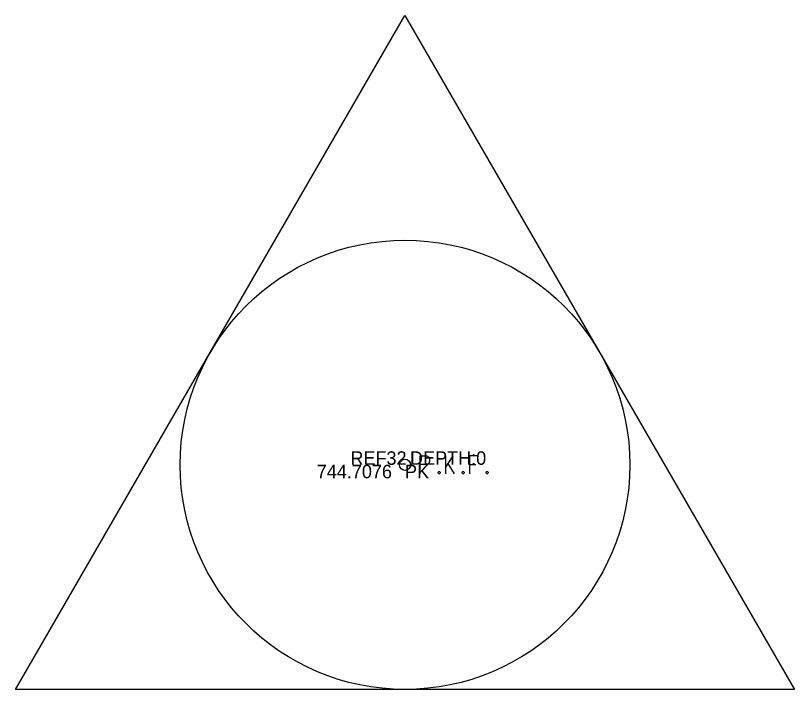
# Model space of a CAD drawing. Extents: x 1775010 to 1779939, y 521137 to 529228.
# Drawn here: x 1775010.409 to 1775013.873, y 521136.832 to 521139.832 of the extents above; entities that cross this region are included whole.
import ezdxf

# ---------------------------------------------------------------- set-up
doc = ezdxf.new("R2010")
doc.units = 0
for name, color, linetype in [('SV_Control_Point', 7, 'Continuous'), ('SV_X_Control_Cells_Found', 7, 'Continuous'), ('SV_X_Text_Comment', 7, 'Continuous'), ('SV_X_Text_Description', 7, 'Continuous'), ('SV_X_Text_Elevation', 7, 'Continuous'), ('SV_X_Text_Name', 7, 'Continuous')]:
    doc.layers.add(name, color=color, linetype=linetype)

msp = doc.modelspace()

# ---------------------------------------------------------------- linework, layer by layer
at = {"layer": 'SV_Control_Point'}
for p, q in [((1775010.4089, 521136.8318), (1775012.141, 521139.8318)), ((1775012.141, 521139.8318), (1775013.8731, 521136.8318)), ((1775012.141, 521137.8318), (1775012.141, 521137.8318)), ((1775013.8731, 521136.8318), (1775010.4089, 521136.8318))]:
    msp.add_line(p, q, dxfattribs=at)
msp.add_circle((1775012.141, 521137.8318), 1, dxfattribs=at)
at = {"layer": 'SV_X_Control_Cells_Found'}
for points in [[(1775012.2091, 521137.7918), (1775012.2091, 521137.8718), (1775012.2355, 521137.8718), (1775012.2383, 521137.8711), (1775012.2421, 521137.8699), (1775012.2438, 521137.8686), (1775012.2454, 521137.8674), (1775012.2476, 521137.8642), (1775012.2493, 521137.8611), (1775012.2504, 521137.856), (1775012.2504, 521137.8485), (1775012.2499, 521137.846), (1775012.2488, 521137.8422), (1775012.2465, 521137.8378), (1775012.2443, 521137.8359), (1775012.2427, 521137.8346), (1775012.2399, 521137.8334), (1775012.2355, 521137.8327), (1775012.2091, 521137.8327)], [(1775012.3215, 521137.8718), (1775012.3215, 521137.7918)], [(1775012.3535, 521137.8718), (1775012.3215, 521137.8208)], [(1775012.4665, 521137.8718), (1775012.4284, 521137.8718), (1775012.4284, 521137.7918)], [(1775012.332, 521137.8371), (1775012.359, 521137.7918)], [(1775012.4284, 521137.8327), (1775012.4554, 521137.8327)], [(1775012.2912, 521137.8025), (1775012.2939, 521137.8025), (1775012.2956, 521137.8012), (1775012.2973, 521137.7987), (1775012.2973, 521137.7956), (1775012.2956, 521137.793), (1775012.2939, 521137.7918), (1775012.2912, 521137.7918), (1775012.2895, 521137.793), (1775012.2879, 521137.7956), (1775012.2879, 521137.7987), (1775012.2895, 521137.8012), (1775012.2912, 521137.8025)], [(1775012.3981, 521137.8025), (1775012.4009, 521137.8025), (1775012.4025, 521137.8012), (1775012.4042, 521137.7987), (1775012.4042, 521137.7956), (1775012.4025, 521137.793), (1775012.4009, 521137.7918), (1775012.3981, 521137.7918), (1775012.3965, 521137.793), (1775012.3948, 521137.7956), (1775012.3948, 521137.7987), (1775012.3965, 521137.8012), (1775012.3981, 521137.8025)], [(1775012.5056, 521137.8025), (1775012.5083, 521137.8025), (1775012.51, 521137.8012), (1775012.5116, 521137.7987), (1775012.5116, 521137.7956), (1775012.51, 521137.793), (1775012.5083, 521137.7918), (1775012.5056, 521137.7918), (1775012.5039, 521137.793), (1775012.5023, 521137.7956), (1775012.5023, 521137.7987), (1775012.5039, 521137.8012), (1775012.5056, 521137.8025)]]:
    msp.add_lwpolyline(points, dxfattribs=at)
msp.add_circle((1775012.141, 521137.8318), 0.0249, dxfattribs=at)

# ---------------------------------------------------------------- texts
at = {"layer": 'SV_X_Text_Comment'}
msp.add_text('PK', height=0.06, dxfattribs=at).set_placement((1775012.141, 521137.7718))
at = {"layer": 'SV_X_Text_Description'}
msp.add_text(' DEPTH:0', height=0.06, dxfattribs=at).set_placement((1775012.141, 521137.8318))
at = {"layer": 'SV_X_Text_Elevation'}
msp.add_text('744.7076', height=0.06, dxfattribs=at).set_placement((1775011.7484, 521137.7718))
at = {"layer": 'SV_X_Text_Name'}
msp.add_text('REF32', height=0.06, dxfattribs=at).set_placement((1775011.8982, 521137.8318))

doc.saveas('drawing.dxf')
